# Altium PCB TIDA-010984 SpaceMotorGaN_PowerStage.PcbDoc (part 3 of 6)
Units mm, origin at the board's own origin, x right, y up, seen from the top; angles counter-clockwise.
Board outline 177.8 x 152.4 mm, 8 copper layers (Top Layer, DC LINK Layer 2, GND Layer 3, 3V3 Layer 4, Layer 5, Layer 6, GND Layer 7, Bottom Layer), stack 1.554 mm thick; 582 components, 280 nets, 1847 pads, 979 vias.
Unrouted connection lines stored in the file: 474.
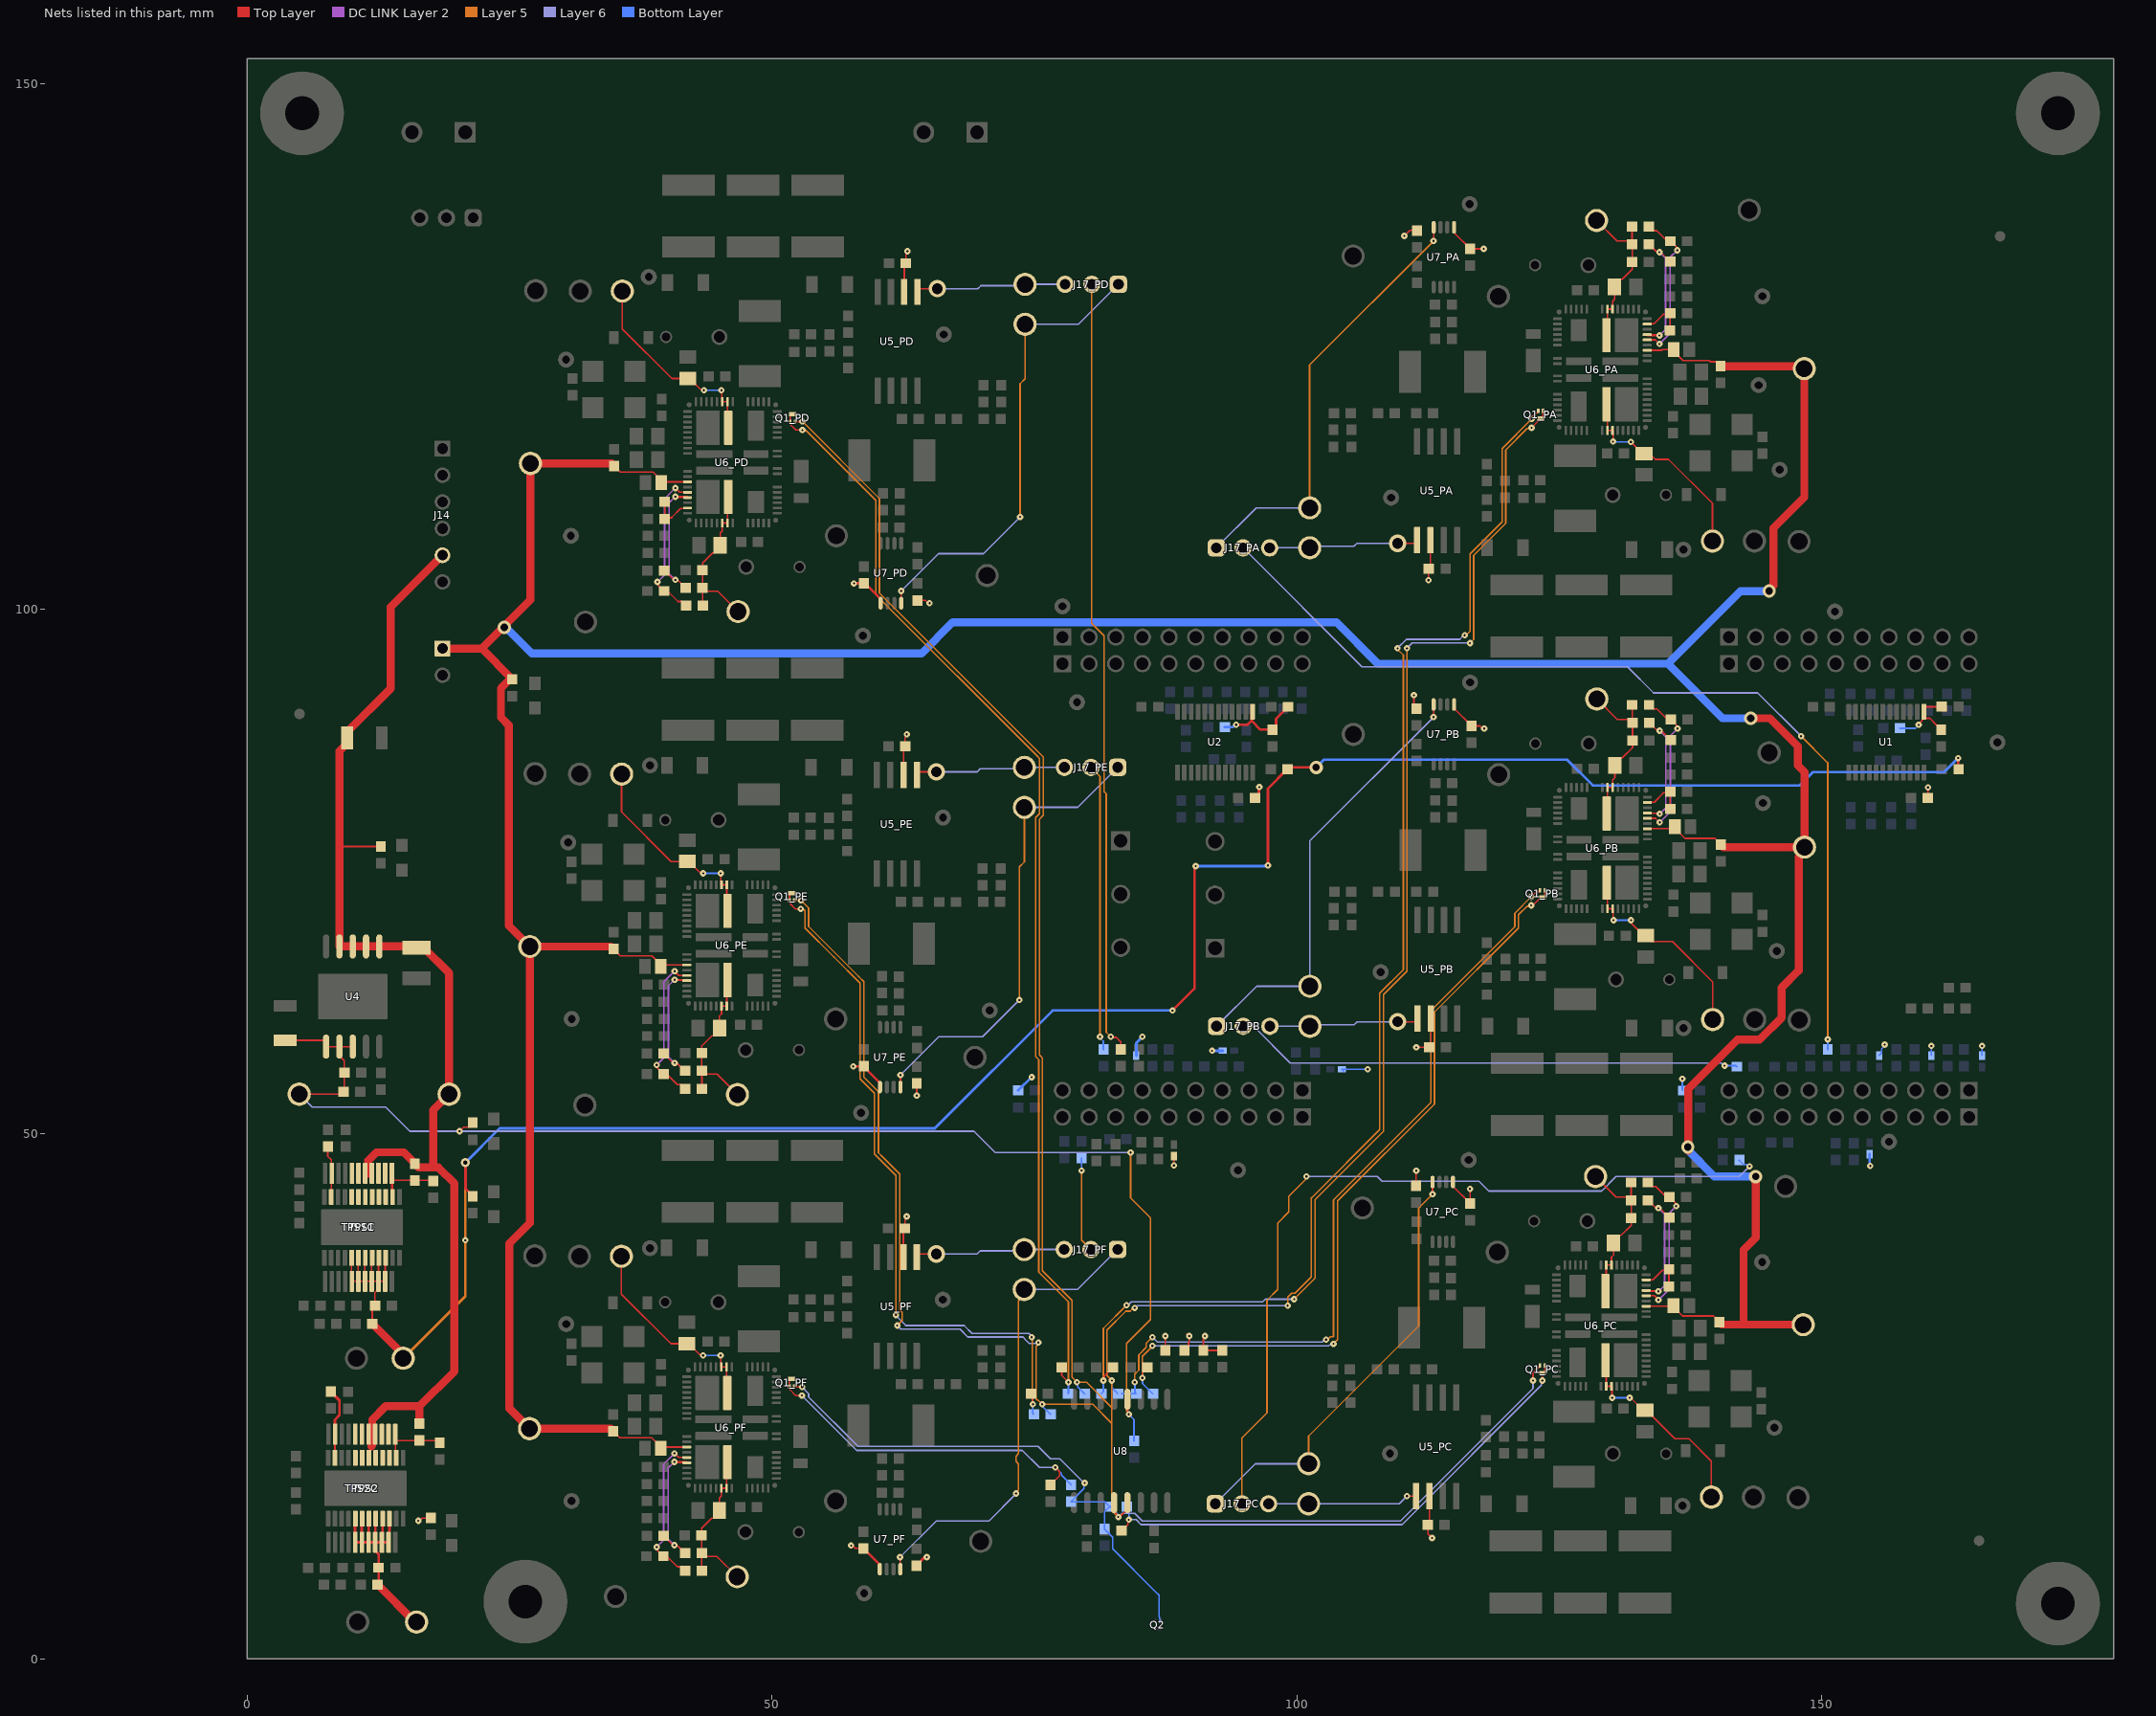
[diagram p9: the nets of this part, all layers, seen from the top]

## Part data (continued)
R78_PA R78_PB R78_PC R78_PD R78_PE R78_PF R80_PA R80_PB R80_PC R80_PD R80_PE R80_PF: library part CMP-0023006-4, "RES, 2.10, 1%, 0.1 W, 0603", Manufacturer=Yageo, Power_W=100mW, Supplier Part Number 1=311-2.10HRCT-ND, TempCo="200 ppm/C", Tolerance_%=1%, Value2=0.1W, Value_Code=2R10, ValueDisplayed=2.10
R82_PA R82_PB R82_PC R82_PD R82_PE R82_PF R83_PA R83_PB R83_PC R83_PD R83_PE R83_PF: library part CMP-0022206-4, "RES, 20.0, 1%, 0.1 W, AEC-Q200 Grade 0, 0603", Manufacturer=Vishay-Dale, Power_W=100mW, Supplier Part Number 1=541-20.0HCT-ND, TempCo="100 ppm/C", Tolerance_%=1%, Value2=0.1W, Value_Code=20R0, ValueDisplayed=20.0
R86_PA R86_PB R86_PC R86_PD R86_PE R86_PF: library part CMP-0023191-5, "RES, 57.6 k, 1%, 0.1 W, 0603", Manufacturer=Yageo, Power_W=100mW, Supplier Part Number 1=311-57.6KHRCT-ND, TempCo="100 ppm/C", Tolerance_%=1%, Value2=0.1W, Value_Code=57k6, ValueDisplayed=57.6k
R91_PA R91_PB R91_PC R91_PD R91_PE R91_PF: library part CMP-0023050-5, "RES, 35.7 k, 1%, 0.1 W, 0603", Manufacturer=Yageo, Power_W=100mW, Supplier Part Number 1=311-35.7KHRCT-ND, TempCo="100 ppm/C", Tolerance_%=1%, Value2=0.1W, Value_Code=35k7, ValueDisplayed=35.7k
R111: library part CMP-0023251-5, "RES, 6.65 k, 1%, 0.1 W, 0603", Manufacturer=Yageo, Power_W=100mW, Supplier Part Number 1=311-6.65KHRCT-ND, TempCo="100 ppm/C", Tolerance_%=1%, Value2=0.1W, Value_Code=6k65, ValueDisplayed=6.65k
R114: library part CMP-0022983-5, "RES, 2.10 k, 1%, 0.1 W, 0603", Manufacturer=Yageo, Power_W=100mW, Supplier Part Number 1=311-2.10KHRCT-ND, TempCo="100 ppm/C", Tolerance_%=1%, Value2=0.1W, Value_Code=2k10, ValueDisplayed=2.10k
TP1 TP3 TP5 TP7_PA TP7_PB TP7_PC TP7_PD TP7_PE TP7_PF TP8_PA TP8_PB TP8_PC TP8_PD TP8_PE TP8_PF TP9_PA TP9_PB TP9_PC TP9_PD TP9_PE TP9_PF TP10 TP11_PA TP11_PB TP11_PC TP11_PD TP11_PE TP11_PF: library part CMP-0055147-2, "Test Point, Multipurpose, Red, TH", Color=Red, Manufacturer="Keystone Electronics", Supplier Part Number 1=36-5010-ND
TP2 TP4: library part CMP-0055149-2, "Test Point, Multipurpose, White, TH", Color=White, Manufacturer="Keystone Electronics", Supplier Part Number 1=36-5012-ND
TP6_PA TP6_PB TP6_PC TP6_PD TP6_PE TP6_PF TP12_PA TP12_PB TP12_PC TP12_PD TP12_PE TP12_PF: library part CMP-0055160-2, "Test Point, Multipurpose, Purple, TH", Color=Purple, Manufacturer="Keystone Electronics", Supplier Part Number 1=36-5129-ND
TP10_PA TP10_PB TP10_PC TP10_PD TP10_PE TP10_PF: library part CMP-0055150-2, "Test Point, Multipurpose, Orange, TH", Color=Orange, Manufacturer="Keystone Electronics", Supplier Part Number 1=36-5013-ND
TP13_PA TP13_PB TP13_PC TP13_PD TP13_PE TP13_PF TP14_PA TP14_PB TP14_PC TP14_PD TP14_PE TP14_PF: library part CMP-0003907-1, "PIGTAIL", Manufacturer="Texas Instruments", PartNumber=TESTPOINT_PIGTAIL
TP16_PA TP16_PB TP16_PC TP16_PD TP16_PE TP16_PF TP17_PA TP17_PB TP17_PC TP17_PD TP17_PE TP17_PF TP18_PA TP18_PB TP18_PC TP18_PD TP18_PE TP18_PF: library part CMP-0055148-2, "Test Point, Multipurpose, Black, TH", Color=Black, Manufacturer="Keystone Electronics", Supplier Part Number 1=36-5011-ND
TPS1 TPS2: library part CMP-0122232-1, "2.25 V to 14-V Input, 2-A, Radiation Hardened LDO Regulator", Dropout Voltage=1000mV, Manufacturer="Texas Instruments", Max Supply Voltage=14V, Min Supply Voltage=2.25V, Nominal Supply Current=8-10mA, Operating Temperature Range="-55°C to +125°C", Output Voltage=0.6-13.9V
TPS1C TPS2C: library part CMP-0032523-3, "2.25 V to 14-V Input, 2-A, Radiation Hardened LDO Regulator", Dropout Voltage=1000mV, Manufacturer="Texas Instruments", Max Supply Voltage=14V, Min Supply Voltage=2.25V, Nominal Supply Current=10mA, Operating Temperature Range="-55°C to +125°C", Output Voltage=0.6-13.9V
U1 U2: library part CMP-0122972-1, "8-Bit Dual-Supply Bus Transceiver With Configurable Voltage Translation and Tri-State Outputs", Digikey Part Number=296-SN54SLC8T245PWTSEPCT-ND, Manufacturer="Texas Instruments", Mouser Part Number=595-54SLC8T245PWTSEP, Nominal Supply Current=70uA, Operating Temperature Range="-55°C to +125°C"
U4: library part CMP-0097443-1, "LDO Regulator Pos 1.21V to 20V 0.75A 10-Pin CFP Tube", Dropout Voltage=0.2V, Manufacturer="Texas Instruments", Max Supply Voltage=20V, Min Supply Voltage=2.9V, Nominal Supply Current=1-28mA, Operating Temperature Range="-55°C to +125°C", Output Voltage=1.21-20V
U5_PA U5_PB U5_PC U5_PD U5_PE U5_PF: library part CMP-0081563-2, "Voltage Output, Unidirectional Measurement Current-Shunt Monitor, HKX0008A (CFP-8)", Alternate Manufacturer="Texas Instruments", Rating=Space
U6_PA U6_PB U6_PC U6_PD U6_PE U6_PF: library part CMP-0121940-3, "200-V, 12-A eGaN Half Bridge Power Stage with Integrated Driver", Manufacturer="Texas Instruments", Max Supply Voltage=16V, Min Supply Voltage=10V, Operating Temperature Range="-55°C to +125°C"
U7_PA U7_PB U7_PC U7_PD U7_PE U7_PF: library part CMP-0075734-1, "High/Low Side, Bi-Directional Zero-Drift Current Sense Amp w/ Enhanced PWM Rejection, PW0008A (TSSOP-8)", Alternate Manufacturer="Texas Instruments", Alternate PartNumber=INA240A1PW
U8: library part CMP-0097071-1, "9-Channel (8-Remote and 1-Local), High-Accuracy Temperature Sensor", Manufacturer="Texas Instruments", Max Supply Voltage=3.6V, Min Supply Voltage=1.7V, Mouser Part Number=595-5962R2021401VXC, Operating Temperature Range="-55°C to +125°C"
ZZ1: library part CMP-0003616-3
ZZ2: library part CMP-0077236-1
ZZ3: library part CMP-0077237-1
ZZ4: library part CMP-0077238-1

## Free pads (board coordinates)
  round 1.524 hole 0.762: 8(30.847,106.96) 8(30.918,15.024) 8(30.932,60.948) 8(58.5,52) 8(58.679,97.465) 8(58.788,6.239) 8(116.38,47.513) 8(116.478,138.569) 8(116.5,93) 8(136.834,60.074) 8(144,121.315) 8(144.337,37.787) 8(144.348,129.784) 8(144.42,81.513) 8(151.27,99.75) 9(30.391,123.75) 9(30.402,31.882) 9(30.594,77.75) 9(66.288,34.206) 9(66.302,80.13) 9(66.37,126.142) 9(107.994,65.421) 9(108.88,19.546) 9(108.978,110.602) 9(145.5,22) 9(145.726,67.426) 9(146,113.25) 10(38.273,131.62) 10(38.379,39.118) 10(38.393,85.089) 10(94.397,46.551) 10(136.743,14.57) 10(136.826,105.643) 10(156.416,49.25) 10(166.75,87.3) 11(79.068,91.113) 12(70.75,61.75) 13(77.676,100.25)

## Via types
v1: diameter 0.61, hole 0.2, Top Layer to Bottom Layer, tented both sides, 306 vias
v2: diameter 0.61, hole 0.203, Top Layer to Bottom Layer, tented both sides, 272 vias
v3: diameter 0.5, hole 0.2, Top Layer to Bottom Layer, tented both sides, 216 vias
v4: diameter 0.5, hole 0.2, Top Layer to Bottom Layer, 66 vias
v5: diameter 0.61, hole 0.2, Top Layer to Bottom Layer, 61 vias
v6: diameter 0.864, hole 0.406, Top Layer to Bottom Layer, tented both sides, 17 vias
v7: diameter 1.651, hole 1.016, Top Layer to Bottom Layer, tented both sides, 12 vias
v8: diameter 0.864, hole 0.406, Top Layer to Bottom Layer, 9 vias
v9: diameter 0.61, hole 0.203, Top Layer to Bottom Layer, 8 vias
v10: diameter 1.27, hole 0.711, Top Layer to Bottom Layer, tented both sides, 5 vias
v11: diameter 0.61, hole 0.2, Top Layer to Bottom Layer, tented top, 2 vias
v12: diameter 1.651, hole 1.016, Top Layer to Bottom Layer, 2 vias
v13: diameter 0.61, hole 0.203, Top Layer to Bottom Layer, tented bottom, 1 vias
v14: diameter 1.27, hole 0.711, Top Layer to Bottom Layer, 1 vias
v15: diameter 1.651, hole 1.016, Top Layer to Bottom Layer, tented top, 1 vias

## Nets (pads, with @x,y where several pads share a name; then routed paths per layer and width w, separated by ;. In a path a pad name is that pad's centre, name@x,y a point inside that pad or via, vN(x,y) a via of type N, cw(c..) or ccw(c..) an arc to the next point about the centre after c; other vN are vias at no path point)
2V: C29.1 C30.1 C57.2 R73.2 R114.2 TP5.1 U4.6 U4.7 U4.8 U8.12 | length 129.7
  Top Layer w0.152: C30.1@3.626,58.906 7.322,58.906 7.529,58.699 U4.6@7.529,58.306 U4.7@8.799,58.306 ; TP5.1@4.973,53.784 8.976,53.784 R73.2@9.192,53.999 9.269,54.076 C29.1@9.269,55.847 9.269,56.986 8.799,57.456 U4.7@8.799,58.306 ; U4.8@10.069,58.306 U4.7@8.799,58.306 ; v5(20.25,50.25) 20.627,50.627 21.101,50.627 21.5,51.026 R114.2@21.5,51.05 ; U8.12@83.934,24.657 83.934,23.356 v1(84,23.29)
  Layer 5 w0.152: v1(84,23.29) 84,23.401 83.794,23.608 83.794,30.044 86.063,32.313 86.063,42 84.169,43.894 v1(84.169,48.22)
  Layer 6 w0.152: TP5.1@4.973,53.784 6.212,52.545 13.205,52.545 15.5,50.25 v5(20.25,50.25) 69.25,50.25 71.28,48.22 v1(84.169,48.22)
  Bottom Layer w0.152: v1(84,23.29) 84.5,22.79 C57.2@84.5,20.744
3V3: C1.1 C11.1 C31_PA.1 C31_PB.1 C31_PC.1 C31_PD.1 C31_PE.1 C31_PF.1 C50_PA.2 C50_PB.2 C50_PC.2 C50_PD.2 C50_PE.2 C50_PF.2 D1.1 D2.1 D3.1 D4.1 D5.1 D6.1 D7.1 D16.1 R1.1 R8.2 R9.2 R12.1 R29.1 R35.2 R36.2 R65.1 R67.1 R94_PA.1 R94_PB.1 R94_PC.1 R94_PD.1 R94_PE.1 R94_PF.1 R96.2 R97.2 R98.2 R99.2 R109.1 R112.2 TP3.1 TPS2.17 TPS2.18 TPS2.19 TPS2.20 TPS2.21 TPS2.22 TPS2C.16 TPS2C.17 TPS2C.18 TPS2C.19 TPS2C.20 TPS2C.21 U1.1 U2.1 U5_PA.6 U5_PB.6 U5_PC.6 U5_PD.6 U5_PE.6 U5_PF.6 U7_PA.5 U7_PB.5 U7_PC.5 U7_PD.5 U7_PE.5 U7_PF.5 | length 123.6
  Top Layer w0.152: v5(16.318,13.154) 16.442,13.154 16.684,13.396 17.456,13.396 R112.2@17.5,13.44 ; v5(57.545,10.789) 57.668,10.789 57.943,10.514 C50_PF.2@58.736,10.514 ; U5_PF.6@62.527,38.262 62.527,40.844 C31_PF.1@62.679,40.996 62.679,41.858 62.837,42.016 v1(62.837,42.14) ; U5_PE.6@62.541,84.186 62.541,86.768 C31_PE.1@62.693,86.92 62.693,87.782 62.851,87.94 v1(62.851,88.064) ; U5_PD.6@62.609,130.198 62.609,132.78 C31_PD.1@62.761,132.932 62.761,133.794 62.919,133.952 v1(62.919,134.076) ; v1(63.797,53.654) R94_PE.1@63.797,54.807 ; R94_PD.1@63.879,100.819 64.624,100.819 64.895,100.547 v1(65.019,100.547) ; R96.2@87.471,29.381 v1(87.471,30.745) ; v1(88.307,47) D7.1@88.307,47.878 ; R97.2@89.285,29.381 89.684,29.78 89.684,30.136 89.75,30.202 v1(89.75,30.745) 89.695,30.745 89.5,30.94 ; v1(91.25,30.745) 91.25,30.621 91.099,30.47 R99.2@91.099,29.381 R98.2@92.913,29.381 ; v5(110.25,135.522) 110.778,136.05 R94_PA.1@111.469,136.05 ; v1(111.155,91.785) 111.155,90.743 R94_PB.1@111.403,90.495 R94_PB.1@111.441,90.532 ; R94_PC.1@111.371,45.05 v5@111.371,46.25 ; v11(111.391,58.235) 112.602,58.235 112.761,58.395 U5_PB.6@112.761,60.977 ; v1(112.556,102.744) 112.556,103.78 C31_PA.1@112.587,103.812 112.739,103.964 U5_PA.6@112.739,106.546 ; U5_PC.6@112.641,15.49 112.641,12.908 C31_PC.1@112.489,12.756 112.489,11.894 v1(112.883,11.5) ; U7_PC.5@114.886,45.413 114.886,45.002 C50_PC.2@116.5,43.388 ; U7_PB.5@114.984,90.899 114.984,90.532 116.642,88.874 C50_PB.2@116.642,88.849 117.481,88.849 117.731,88.6 v5(117.855,88.6) ; U7_PA.5@114.984,136.35 115.031,136.303 115.031,135.794 116.5,134.325 C50_PA.2@116.5,134.3 v5(117.817,134.3) ; C50_PC.2@116.5,43.363 C50_PC.2@116.5,43.388 ; v5(116.5,44.75) C50_PC.2@116.5,43.388 ; v1@159.173,88.961 159.592,89.38 159.592,90.067 U1.1@159.741,90.216 ; R8.2@160.116,82 160.116,81.952 160.131,81.936 v1(160.131,83) ; R1.1@161.386,88.509 161.386,88.534 160.988,88.933 160.963,88.933 160.304,89.592 159.889,89.592 159.741,89.74 U1.1@159.741,90.216 ; R9.2@161.45,90.683 159.889,90.683 159.741,90.535 U1.1@159.741,90.216
  Top Layer w0.254: TPS2.17@10.317,13.34 10.296,13.32 10.296,11.116 10.276,11.095 TPS2C.16@10.308,11.095 TPS2C.17@10.911,11.095 ; TPS2.18@10.967,13.34 10.939,13.312 10.939,11.123 TPS2C.17@10.911,11.095 ; TPS2.19@11.617,13.34 11.581,13.305 11.581,11.131 TPS2C.18@11.546,11.095 ; TPS2.20@12.267,13.34 12.224,13.297 TPS2C.19@12.224,11.095 ; R67.1@12.442,7.069 R67.1@12.417,7.069 12.541,7.193 R65.1@12.541,8.684 12.541,9.953 12.224,10.27 TPS2C.19@12.224,11.095 ; TPS2.21@12.917,13.34 12.917,11.979 12.816,11.878 TPS2C.20@12.816,11.095 ; TPS2.22@13.567,13.34 13.567,12.227 13.541,12.201 13.541,11.186 13.451,11.095 TPS2C.20@12.848,11.095 TPS2C.20@12.816,11.095 ; TP3.1@16.01,3.5 TP3.1@16.153,3.5 ; v1(57.75,56.418) 58.73,56.418 C50_PE.2@58.75,56.438 ; v1(57.818,102.43) 58.73,102.43 C50_PD.2@58.75,102.45 ; C50_PF.2@58.736,10.489 60.282,8.943 U7_PF.5@60.282,8.536 ; C50_PE.2@58.75,56.413 60.296,54.867 U7_PE.5@60.296,54.46 ; C50_PD.2@58.75,102.425 59.098,102.077 59.234,102.077 60.364,100.947 U7_PD.5@60.364,100.547 ; R94_PE.1@63.691,54.701 R94_PE.1@63.797,54.807 ; R94_PF.1@63.783,8.882 63.783,8.907 64.49,9.614 64.682,9.614 v5(64.75,9.682) ; v1(94.227,88.968) 95.301,88.968 95.693,89.359 ; U2.1@95.791,90.216 95.693,90.118 95.693,89.359 ; R35.2@96.195,81.811 R35.2@96.006,82 96.031,82 96.379,82.348 96.379,82.971 v1(96.442,83.035) ; R29.1@97.681,88.484 R29.1@97.681,88.509 ; R36.2@99.189,90.682 99.164,90.682 98.029,89.547 98.029,88.857 R29.1@97.681,88.509 ; TPS2C.17@10.911,11.095 TPS2C.17@10.943,11.095 TPS2C.18@11.546,11.095 ; TPS2C.18@11.546,11.095 TPS2C.18@11.578,11.095 TPS2C.19@12.213,11.095 TPS2C.19@12.224,11.095 ; TPS2C.19@12.224,11.095 TPS2C.20@12.816,11.095 ; 95.693,89.359 96.543,88.509 R29.1@97.681,88.509
  Top Layer w0.762: R67.1@12.417,7.069 12.442,7.069 16.01,3.5 TP3.1@16.153,3.5
  Layer 6 w0.254: TP3.1@15.592,3.5 TP3.1@16.153,3.5
  Bottom Layer w0.152: D16.1@104.449,56 D16.1@104.3,56.149 v9(106.75,56.149) ; v1(136.723,55.25) 136.723,54.223 R12.1@136.804,54.142 ; D2.1@155.497,57.464 155.721,57.688 155.721,58.097 156,58.376 v1(156,58.5) ; C1.1@157.471,88.636 158.925,88.636 v1(159.25,88.961) ; D3.1@160.447,57.464 v1(160.447,58.376) ; D1.1@165.29,57.464 v1(165.29,58.376)
  Bottom Layer w0.254: R109.1@73.45,54.142 73.475,54.142 74.727,55.394 v9(74.75,55.394) ; D5.1@84.709,57.462 84.709,58.662 v1(85.296,59.248) ; v1@91.844,58.036 91.844,58.006 v1(91.931,57.919) D6.1@92.939,57.919 ; C11.1@93.166,88.75 93.914,88.75 94.132,88.968 v1(94.227,88.968) ; D4.1@154.577,48.069 154.577,46.993 v1(154.632,46.938)
  other v5: 111.391,46.497
5V: R2.1 R30.1 R55.1 R59.1 R111.2 TP1.1 TPS1.17 TPS1.18 TPS1.19 TPS1.20 TPS1.21 TPS1.22 TPS1C.16 TPS1C.17 TPS1C.18 TPS1C.19 TPS1C.20 TPS1C.21 | length 222.6
  Top Layer w0.152: TPS1.17@9.968,38.198 9.947,38.178 9.947,35.974 9.927,35.953 TPS1C.17@10.562,35.953 ; TPS1.18@10.618,38.198 10.59,38.17 10.59,35.981 TPS1C.17@10.562,35.953 ; TPS1.19@11.268,38.198 11.232,38.163 11.232,35.989 TPS1C.18@11.197,35.953 ; TPS1.20@11.918,38.198 11.875,38.155 11.875,35.996 TPS1C.19@11.832,35.953 ; R59.1@11.932,31.892 11.932,33.382 R55.1@12.192,33.642 12.192,34.896 12.467,35.171 TPS1C.20@12.467,35.953 ; TPS1.21@12.568,38.198 12.517,38.148 12.517,36.004 TPS1C.20@12.467,35.953 ; TPS1.22@13.218,38.198 13.16,38.14 13.16,36.011 13.102,35.953 TPS1C.20@12.467,35.953 ; TPS1C.17@10.562,35.953 TPS1C.18@11.197,35.953 ; TPS1C.18@11.197,35.953 TPS1C.19@11.832,35.953 ; TPS1C.19@11.832,35.953 TPS1C.20@12.467,35.953
  Top Layer w0.254: R59.1@11.932,31.892 R59.1@11.957,31.892 ; TP1.1@14.875,28.624 TP1.1@14.875,28.974 ; v6(20.792,47.25) 20.807,47.235 20.807,44.768 21.5,44.075 R111.2@21.5,44.05 ; v1(88.155,61.75) 90.25,63.845 90.25,75.282 90.376,75.408 v1(90.376,75.5) ; v1(97.25,75.576) 97.25,82.893 R30.1@99.104,84.747 ; R30.1@99.129,84.747 99.293,84.911 v14(101.84,84.911) ; v1(163,85.792) 163,84.797 R2.1@163.05,84.747
  Top Layer w0.762: R59.1@11.957,31.892 TP1.1@14.875,28.974
  Layer 5 w0.254: TP1.1@14.875,28.624 20.792,34.541 v1(20.792,39.867) v6(20.792,47.25)
  Layer 6 w0.254: v1(20.792,39.867) v1@20.888,39.867
  Bottom Layer w0.254: v6(20.792,47.25) 24.056,50.514 65.514,50.514 76.75,61.75 v1(88.155,61.75) ; v1(90.376,75.5) 97.101,75.5 97.177,75.576 v1(97.25,75.576) ; v14(101.84,84.911) 102.576,85.647 125.75,85.647 128.206,83.191 147.891,83.191 149.158,84.457 161.665,84.457 v1(163,85.792)
12Vp: C23.1 C24.1 J14.5 R54.2 R64.2 R102.2 TP10.1 TPS1.3 TPS1.4 TPS1.5 TPS1.6 TPS1.7 TPS1.8 TPS1C.2 TPS1C.3 TPS1C.4 TPS1C.5 TPS1C.6 TPS1C.7 TPS2.3 TPS2.4 TPS2.5 TPS2.6 TPS2.7 TPS2.8 TPS2C.2 TPS2C.3 TPS2C.4 TPS2C.5 TPS2C.6 TPS2C.7 U4.1 U4.2 U4.3 U4.4 | length 118.4
  Top Layer w0.152: 8.799,77.472 8.903,77.369 R102.2@12.75,77.369
  Top Layer w0.762: 11.546,46.206 11.546,47.467 12.329,48.25 14.931,48.25 15.985,47.196 R54.2@15.985,47.171 ; 11.832,20.213 11.932,20.313 11.932,22.77 13.229,24.068 16.429,24.068 ; R54.2@16.333,46.798 17.725,46.798 ; R64.2@16.429,22.386 16.429,24.068 ; J14.5@18.62,105.115 13.694,100.189 13.694,92.436 9.533,88.275 C24.1@9.533,87.725 9.533,87.175 8.799,86.441 8.799,77.472 U4.4@8.799,67.856 U4.3@10.069,67.856 U4.2@11.339,67.856 U4.1@12.609,67.856 16.01,67.856 C23.1@16.142,67.724 16.842,67.724 19.25,65.316 TP10.1@19.25,53.784 17.725,52.259 17.725,46.798 ; 16.429,24.068 19.75,27.389 19.75,45.28 18.232,46.798 17.725,46.798
12Vs: C44_PA.2 C44_PB.2 C44_PC.2 C44_PD.2 C44_PE.2 C44_PF.2 J15.1 R78_PA.2 R78_PB.2 R78_PC.2 R78_PD.2 R78_PE.2 R78_PF.2 R110.2 TP7_PA.1 TP7_PB.1 TP7_PC.1 TP7_PD.1 TP7_PE.1 TP7_PF.1 U6_PA.13 U6_PB.13 U6_PC.13 U6_PD.13 U6_PE.13 U6_PF.13 | length 429.2
  Top Layer w0.152: R78_PF.2@34.892,21.683 34.892,21.658 35.291,21.259 35.316,21.259 35.531,21.044 38.549,21.044 39.406,20.187 C44_PF.2@39.406,20.037 ; R78_PE.2@34.906,67.608 34.906,67.583 35.304,67.184 35.329,67.184 35.545,66.968 38.563,66.968 39.42,66.112 C44_PE.2@39.42,65.962 ; R78_PD.2@34.974,113.619 34.974,113.594 35.373,113.196 35.398,113.196 35.571,113.022 38.691,113.022 38.978,112.734 38.978,112.508 C44_PD.2@39.452,112.034 ; C44_PF.2@39.467,19.977 39.663,20.173 U6_PF.13@41.884,20.173 ; C44_PE.2@39.48,65.901 39.677,66.097 U6_PE.13@41.898,66.097 ; C44_PD.2@39.488,111.973 C44_PD.2@39.488,112.123 ; C44_PD.2@39.549,111.913 39.745,112.109 U6_PD.13@41.966,112.109 ; U6_PC.13@133.284,33.579 135.655,33.579 135.798,33.722 135.798,33.59 136.36,33.027 136.377,33.027 136.56,32.844 136.56,32.837 136.743,32.654 139.691,32.654 139.852,32.492 139.877,32.492 140.276,32.094 R78_PC.2@140.276,32.069 ; U6_PA.13@133.382,124.635 134.766,124.635 134.845,124.713 C44_PA.2@135.888,124.713 135.888,124.563 136.797,123.653 139.298,123.653 139.403,123.548 139.975,123.548 140.374,123.149 R78_PA.2@140.374,123.124 ; U6_PB.13@133.404,79.066 135.775,79.066 135.918,79.209 136.986,78.141 139.836,78.141 140.609,77.368 R78_PB.2@140.609,77.318
  Top Layer w0.762: J15.1@18.62,96.225 22.35,96.225 ; R110.2@24.934,93.181 24.194,92.441 24.194,89.668 24.934,88.927 24.934,69.842 TP7_PE.1@26.932,67.845 ; R110.2@25.25,93.325 22.35,96.225 ; R78_PF.2@34.892,21.683 34.892,21.708 34.798,21.802 34.773,21.802 34.654,21.921 TP7_PF.1@26.918,21.921 25,23.839 25,39.568 26.932,41.499 TP7_PE.1@26.932,67.845 ; R78_PE.2@34.906,67.608 34.906,67.633 34.812,67.727 34.787,67.727 34.668,67.845 TP7_PE.1@26.932,67.845 ; R78_PD.2@34.974,113.619 34.974,113.644 34.88,113.738 34.855,113.738 34.736,113.857 TP7_PD.1@27,113.857 27,100.876 22.35,96.225 ; v10@137.307,48.406 137.307,54.31 141.966,58.969 144.082,58.969 146.184,61.071 146.184,63.91 147.822,65.548 147.822,76.378 148.37,76.926 TP7_PB.1@148.37,77.318 ; R78_PC.2@140.276,32.069 140.276,32.044 140.488,31.831 143.716,31.831 TP7_PC.1@148.25,31.831 ; R78_PA.2@140.374,123.124 148.11,123.124 TP7_PA.1@148.348,122.887 148.348,110.635 145.404,107.691 145.404,102.245 145,101.841 v10(145,101.704) ; R78_PB.2@140.609,77.318 TP7_PB.1@148.37,77.318 ; 142.568,31.831 142.568,38.945 143.716,40.093 v10(143.716,45.938) ; v10(143.25,89.592) 145.068,89.592 147.75,86.909 147.75,85.092 148.37,84.471 TP7_PB.1@148.37,77.318
  Bottom Layer w0.762: v10(24.5,98.25) 24.637,98.25 27.137,95.75 64.25,95.75 67.228,98.728 103.772,98.728 107.718,94.782 135.356,94.782 ; v10@137.307,48.406 139.776,45.938 v10(143.716,45.938) ; v10(143.25,89.592) 140.547,89.592 135.356,94.782 ; v10(145,101.704) 142.277,101.704 135.356,94.782
  other v10: 137.25,48.75
BP5H_PA: C55_PA.2 TP11_PA.1 U6_PA.58 U6_PA.59 U6_PA.74 | length 19.2
  Top Layer w0.152: U6_PA.74@129.507,119.492 129.583,119.416 U6_PA.58@129.583,117.01 U6_PA.59@130.083,117.01 130.132,116.961 v1(130.132,115.94) v1@130.155,115.917 ; v1(131.819,115.917) 131.819,115.909 132.918,114.81 C55_PA.2@133.083,114.81 ; C55_PA.2@133.591,114.81 134.149,114.251 135.411,114.251 139.598,110.064 TP11_PA.1@139.598,106.46
  Bottom Layer w0.152: v1@130.193,115.955 130.155,115.917 v1(131.819,115.917)
BP5H_PB: C55_PB.2 TP11_PB.1 U6_PB.58 U6_PB.59 U6_PB.74 | length 19.7
  Top Layer w0.152: U6_PB.74@129.529,73.923 129.605,73.847 U6_PB.58@129.605,71.441 U6_PB.59@130.105,71.441 130.154,71.392 130.154,70.371 v1(130.177,70.348) ; v1@131.841,70.34 v1(131.841,70.348) 131.929,70.26 131.929,70.018 133.074,68.873 C55_PB.2@133.239,68.873 133.798,68.314 135.784,68.314 139.62,64.478 TP11_PB.1@139.62,60.891
  Bottom Layer w0.152: v1(130.177,70.348) v1(131.841,70.348)
BP5H_PC: C55_PC.2 TP11_PC.1 U6_PC.58 U6_PC.59 U6_PC.74 | length 19.6
  Top Layer w0.152: U6_PC.74@129.409,28.436 129.485,28.36 U6_PC.58@129.485,25.954 U6_PC.59@129.985,25.954 130.034,25.905 130.034,24.884 v1(130.057,24.861) ; v1@131.721,24.853 v1(131.721,24.861) 131.808,24.861 133.007,23.662 C55_PC.2@133.172,23.662 133.337,23.662 136.033,20.966 137.363,20.966 139.5,18.828 TP11_PC.1@139.5,15.404
  Bottom Layer w0.152: v1@130.095,24.9 v1(130.057,24.861) v1(131.721,24.861)
BP5H_PD: C55_PD.2 TP11_PD.1 U6_PD.58 U6_PD.59 U6_PD.74 | length 19.7
  Top Layer w0.152: TP11_PD.1@35.75,130.284 35.75,126.679 40.477,121.953 C55_PD.2@41.992,121.953 42.157,121.953 43.195,120.914 43.442,120.914 v1(43.529,120.827) v1@43.529,120.835 ; v1(45.193,120.827) 45.216,120.804 45.216,119.783 U6_PD.59@45.265,119.734 U6_PD.58@45.765,119.734 45.765,117.328 U6_PD.74@45.841,117.252
  Bottom Layer w0.152: v1(43.529,120.827) v1(45.193,120.827) v1@45.155,120.788
BP5H_PE: C55_PE.2 TP11_PE.1 U6_PE.58 U6_PE.59 U6_PE.74 | length 19.7
  Top Layer w0.152: TP11_PE.1@35.682,84.272 35.682,80.667 40.408,75.941 C55_PE.2@41.924,75.941 42.089,75.941 43.127,74.903 43.373,74.903 v1(43.461,74.815) v1@43.461,74.823 ; v1(45.125,74.815) 45.148,74.792 45.148,73.771 U6_PE.59@45.197,73.722 U6_PE.58@45.697,73.722 45.697,71.316 U6_PE.74@45.773,71.24
  Bottom Layer w0.152: v1(43.461,74.815) v1(45.125,74.815) v1@45.086,74.777
BP5H_PF: C55_PF.2 TP11_PF.1 U6_PF.58 U6_PF.59 U6_PF.74 | length 19.7
  Top Layer w0.152: TP11_PF.1@35.668,38.348 35.668,34.743 40.395,30.016 C55_PF.2@41.91,30.016 42.075,30.016 43.113,28.978 43.359,28.978 v1(43.447,28.891) v1@43.447,28.899 ; v1(45.111,28.891) 45.134,28.868 45.134,27.847 U6_PF.59@45.183,27.798 U6_PF.58@45.683,27.798 45.683,25.392 U6_PF.74@45.759,25.316
  Bottom Layer w0.152: v1(43.447,28.891) v1(45.111,28.891) v1@45.073,28.852
BP5L_PA: C52_PA.2 R81_PA.2 R84_PA.1 R87_PA.1 TP9_PA.1 U6_PA.26 U6_PA.27 U6_PA.69 | length 16.1
  Top Layer w0.152: TP9_PA.1@128.565,136.994 130.513,135.045 131.637,135.045 R87_PA.1@131.949,134.734 ; U6_PA.69@129.507,126.078 129.583,126.154 U6_PA.27@129.583,128.56 U6_PA.26@130.083,128.56 130.083,129.311 130.271,129.499 C52_PA.2@130.271,130.675 130.271,130.84 130.83,131.399 130.995,131.399 131.958,132.362 R81_PA.2@131.958,133.046 131.958,134.725 R87_PA.1@131.949,134.734 ; R84_PA.1@131.937,136.43 131.949,136.418 R87_PA.1@131.949,134.734
BP5L_PB: C52_PB.2 R81_PB.2 R84_PB.1 R87_PB.1 TP9_PB.1 U6_PB.26 U6_PB.27 U6_PB.69 | length 16.1
  Top Layer w0.152: TP9_PB.1@128.587,91.425 130.535,89.476 131.659,89.476 R87_PB.1@131.971,89.165 ; U6_PB.69@129.529,80.509 129.605,80.585 U6_PB.27@129.605,82.991 U6_PB.26@130.105,82.991 130.105,83.742 130.293,83.93 C52_PB.2@130.293,85.106 130.293,85.271 130.852,85.83 131.017,85.83 131.98,86.793 R81_PB.2@131.98,87.477 131.98,89.156 R87_PB.1@131.971,89.165 ; R84_PB.1@131.959,90.861 131.971,90.849 R87_PB.1@131.971,89.165
BP5L_PC: C52_PC.2 R81_PC.2 R84_PC.1 R87_PC.1 TP9_PC.1 U6_PC.26 U6_PC.27 U6_PC.69 | length 16.1
  Top Layer w0.152: TP9_PC.1@128.467,45.938 130.415,43.99 131.539,43.99 R87_PC.1@131.851,43.678 ; U6_PC.69@129.409,35.022 129.485,35.098 U6_PC.27@129.485,37.504 U6_PC.26@129.985,37.504 129.985,38.256 130.173,38.444 C52_PC.2@130.173,39.619 130.173,39.784 130.732,40.343 130.897,40.343 131.86,41.306 R81_PC.2@131.86,41.99 131.86,43.669 R87_PC.1@131.851,43.678 ; R84_PC.1@131.839,45.374 131.851,45.362 R87_PC.1@131.851,43.678
BP5L_PD: C52_PD.2 R81_PD.2 R84_PD.1 R87_PD.1 TP9_PD.1 U6_PD.26 U6_PD.27 U6_PD.69 | length 16.1
  Top Layer w0.152: R84_PD.1@43.411,100.314 43.399,100.326 R87_PD.1@43.399,102.01 ; U6_PD.69@45.841,110.666 45.765,110.59 U6_PD.27@45.765,108.184 U6_PD.26@45.265,108.184 45.265,107.433 45.077,107.245 C52_PD.2@45.077,106.069 45.077,105.904 44.518,105.345 44.353,105.345 43.39,104.382 R81_PD.2@43.39,103.698 43.39,102.019 R87_PD.1@43.399,102.01 ; TP9_PD.1@46.783,99.75 44.835,101.698 43.711,101.698 R87_PD.1@43.399,102.01
BP5L_PE: C52_PE.2 R81_PE.2 R84_PE.1 R87_PE.1 TP9_PE.1 U6_PE.26 U6_PE.27 U6_PE.69 | length 16.1
  Top Layer w0.152: R84_PE.1@43.343,54.302 43.331,54.314 R87_PE.1@43.331,55.998 ; U6_PE.69@45.773,64.654 45.697,64.578 U6_PE.27@45.697,62.172 U6_PE.26@45.197,62.172 45.197,61.421 45.009,61.233 C52_PE.2@45.009,60.057 45.009,59.892 44.45,59.333 44.285,59.333 43.322,58.37 R81_PE.2@43.322,57.686 43.322,56.007 R87_PE.1@43.331,55.998 ; TP9_PE.1@46.715,53.738 44.766,55.687 43.642,55.687 R87_PE.1@43.331,55.998
BP5L_PF: C52_PF.2 R81_PF.2 R84_PF.1 R87_PF.1 TP9_PF.1 U6_PF.26 U6_PF.27 U6_PF.69 | length 16.1
  Top Layer w0.152: R84_PF.1@43.329,8.378 43.317,8.39 R87_PF.1@43.317,10.074 ; U6_PF.69@45.759,18.73 45.683,18.654 U6_PF.27@45.683,16.248 U6_PF.26@45.183,16.248 45.183,15.496 44.995,15.308 C52_PF.2@44.995,14.133 44.995,13.968 44.436,13.409 44.271,13.409 43.308,12.446 R81_PF.2@43.308,11.762 43.308,10.083 R87_PF.1@43.317,10.074 ; TP9_PF.1@46.701,7.814 44.753,9.762 43.629,9.762 R87_PF.1@43.317,10.074
CL3: R68.2 TPS2.11 TPS2C.10 | length 6.8
  Top Layer w0.152: TPS2.11@8.367,19.14 8.369,19.142 TPS2C.10@8.369,21.383
  Top Layer w0.254: R68.2@8.004,25.441 8.004,25.416 8.806,24.614 8.806,23.206 8.371,22.77 8.371,21.385 TPS2C.10@8.369,21.383
CL5: R60.2 TPS1.11 TPS1C.10 | length 4.9
  Top Layer w0.152: R60.2@7.712,48.786 7.69,48.763 7.69,47.86 8.022,47.528 8.022,46.243 8.02,46.241 8.02,44 TPS1.11@8.018,43.998
CS_HiSide_PA: J17_PA.3 TP6_PA.1 U5_PA.5 | length 14.6
  Top Layer w0.152: v7(109.598,106.244) 111.245,106.244 111.469,106.468 U5_PA.5@111.469,106.546
  Layer 5 w0.152: TP6_PA.1@101.228,105.821 TP6_PA.1@101.364,105.958
  Layer 6 w0.152: J17_PA.3@97.418,105.821 TP6_PA.1@101.228,105.821 101.364,105.958 105.442,105.958 105.728,106.244 v7(109.598,106.244)
CS_HiSide_PB: J17_PB.3 TP6_PB.1 U5_PB.5 | length 14.6
  Top Layer w0.152: v7(109.62,60.675) 111.267,60.675 111.491,60.899 U5_PB.5@111.491,60.977
  Layer 5 w0.152: TP6_PB.1@101.25,60.252 TP6_PB.1@101.386,60.389
  Layer 6 w0.152: J17_PB.3@97.44,60.252 TP6_PB.1@101.25,60.252 101.386,60.389 105.464,60.389 105.75,60.675 v7(109.62,60.675)
CS_HiSide_PC: J17_PC.3 TP6_PC.1 U5_PC.5 | length 14.6
  Top Layer w0.152: v1(110.49,15.49) U5_PC.5@111.371,15.49
  Layer 5 w0.152: TP6_PC.1@101.13,14.766 TP6_PC.1@101.266,14.902
  Layer 6 w0.152: J17_PC.3@97.32,14.766 TP6_PC.1@101.13,14.766 109.766,14.766 v1(110.49,15.49) v1@110.5,15.5
CS_HiSide_PD: J17_PD.3 TP6_PD.1 U5_PD.5 | length 14.6
  Top Layer w0.152: U5_PD.5@63.879,130.198 63.879,130.276 64.103,130.5 v7(65.75,130.5)
  Layer 5 w0.152: TP6_PD.1@73.984,130.786 TP6_PD.1@74.12,130.923
  Layer 6 w0.152: v7(65.75,130.5) 69.62,130.5 69.906,130.786 73.984,130.786 TP6_PD.1@74.12,130.923 J17_PD.3@77.93,130.923
CS_HiSide_PE: J17_PE.3 TP6_PE.1 U5_PE.5 | length 14.6
  Top Layer w0.152: U5_PE.5@63.811,84.186 63.811,84.264 64.034,84.488 v7(65.682,84.488)
  Layer 5 w0.152: TP6_PE.1@73.916,84.774 TP6_PE.1@74.052,84.911
  Layer 6 w0.152: v7(65.682,84.488) 69.551,84.488 69.838,84.774 73.916,84.774 TP6_PE.1@74.052,84.911 J17_PE.3@77.862,84.911
CS_HiSide_PF: J17_PF.3 TP6_PF.1 U5_PF.5 | length 14.6
  Top Layer w0.152: U5_PF.5@63.797,38.262 63.797,38.34 64.021,38.564 v15(65.668,38.564)
  Layer 5 w0.152: TP6_PF.1@73.902,38.85 TP6_PF.1@74.038,38.986
  Layer 6 w0.152: v15(65.668,38.564) 69.538,38.564 69.824,38.85 73.902,38.85 TP6_PF.1@74.038,38.986 J17_PF.3@77.848,38.986
CS_InPhase_PA: J17_PA.1 TP12_PA.1 U7_PA.8 | length 42.3
  Top Layer w0.152: v5(113.034,135.045) U7_PA.8@113.034,136.35
  Layer 5 w0.152: TP12_PA.1@101.228,109.631 101.228,123.239 v5(113.034,135.045) v5@113.034,135.25
  Layer 6 w0.152: J17_PA.1@92.338,105.821 96.148,109.631 TP12_PA.1@101.228,109.631
CS_InPhase_PB: J17_PB.1 TP12_PB.1 U7_PB.8 | length 42.2
  Top Layer w0.152: v5(113.034,89.695) U7_PB.8@113.034,90.899
  Layer 6 w0.152: J17_PB.1@92.36,60.252 96.17,64.062 TP12_PB.1@101.25,64.062 101.25,77.911 v5(113.034,89.695)
CS_InPhase_PC: J17_PC.1 TP12_PC.1 U7_PC.8 | length 42.2
  Top Layer w0.152: v5(112.936,44.25) U7_PC.8@112.936,45.413
  Layer 5 w0.152: TP12_PC.1@101.13,18.576 101.13,21.214 111.614,31.697 111.614,42.928 v5(112.936,44.25)
  Layer 6 w0.152: J17_PC.1@92.24,14.766 96.05,18.576 TP12_PC.1@101.13,18.576
CS_InPhase_PD: J17_PD.1 TP12_PD.1 U7_PD.8 | length 44.4
  Top Layer w0.152: U7_PD.8@62.315,100.548 v5@62.315,101.712
  Layer 5 w0.152: v1(73.649,108.762) 73.649,121.454 74.12,121.925 TP12_PD.1@74.12,127.113
  Layer 6 w0.152: v5(62.315,101.713) 65.864,105.262 70.149,105.262 v1(73.649,108.762) ; TP12_PD.1@74.12,127.113 79.2,127.113 J17_PD.1@83.01,130.923
CS_InPhase_PE: J17_PE.1 TP12_PE.1 U7_PE.8 | length 44.5
  Top Layer w0.152: U7_PE.8@62.246,54.46 v5(62.246,55.607)
  Layer 5 w0.152: v1(73.581,62.75) 73.581,75.442 74.052,75.913 TP12_PE.1@74.052,81.101
  Layer 6 w0.152: v5(62.246,55.607) 65.889,59.25 70.081,59.25 v1(73.581,62.75) ; TP12_PE.1@74.052,81.101 79.132,81.101 J17_PE.1@82.942,84.911
CS_InPhase_PF: J17_PF.1 TP12_PF.1 U7_PF.8 | length 45.2
  Top Layer w0.152: v5(62.21,9.682) 62.221,9.672 62.221,8.547 U7_PF.8@62.232,8.536
  Layer 5 w0.152: v5(73.25,15.75) 73.25,15.818 73.5,16.068 73.5,18.561 73.25,18.811 73.25,19.293 73.5,19.543 73.5,34.081 74.038,34.62 TP12_PF.1@74.038,35.176
  Layer 6 w0.152: v5(62.21,9.682) 65.665,13.137 70.675,13.137 73.25,15.712 v5(73.25,15.75) ; TP12_PF.1@74.038,35.176 79.118,35.176 J17_PF.1@82.928,38.986
CS_PA: J17_PA.2 R7.1 | length 91.5
  Layer 5 w0.152: v1(148.043,87.869) 150.583,85.329 ; v1(150.583,59) 150.583,85.366
  Layer 6 w0.152: J17_PA.2@94.878,105.821 106.199,94.5 131.5,94.5 134,92 143.912,92 v1(148.043,87.869)
  Bottom Layer w0.152: R7.1@150.583,58.037 v1(150.583,59)
CS_PB: J17_PB.2 R10.1 | length 48.6
  Layer 6 w0.152: J17_PB.2@94.9,60.252 94.971,60.181 95.954,60.181 99.385,56.75 140.432,56.75 140.682,56.5 v1(140.75,56.5)
  Bottom Layer w0.152: v1(140.75,56.5) 141.836,56.5 R10.1@141.929,56.406
CS_PC: J17_PC.2 R11.1 | length 78.6
  Layer 5 w0.152: J17_PC.2@94.78,14.766 94.78,21.03 97.169,23.419 97.169,34.16 98.185,35.176 98.185,41.498 99.25,42.563 99.25,44.058 100.831,45.639 v1@100.831,45.851
  Layer 6 w0.152: v1(100.919,45.938) 107.678,45.938 108.116,45.5 117.355,45.5 118.298,44.557 129.039,44.557 130.42,45.938 142.151,45.938 v1(143.127,46.914)
  Bottom Layer w0.152: R11.1@142.157,47.495 142.157,47.47 142.556,47.071 142.846,47.071 143.003,46.914 v1(143.127,46.914)
CS_PD: J17_PD.2 R34.1 | length 74.3
  Top Layer w0.152: v1(82.287,59.25) 82.351,59.186 82.82,59.186 83.253,58.753 R34.1@83.253,58.036
  Layer 5 w0.152: J17_PD.2@80.47,130.923 80.47,98.625 81.655,97.441 81.655,82.594 81.855,82.393 81.855,59.681 v1(82.287,59.25)
CS_PE: J17_PE.2 R37.1 | length 27.4
  Layer 5 w0.152: J17_PE.2@80.402,84.911 81.25,84.062 v1(81.25,59.25)
  Bottom Layer w0.152: v1(81.25,59.25) 81.25,59.155 81.58,58.825 R37.1@81.58,58.036
CS_PF: J17_PF.2 R38.1 | length 9.1
  Layer 5 w0.152: v1(79.5,46.5) 79.5,39.874 J17_PF.2@80.388,38.986
  Bottom Layer w0.152: v1(79.5,46.5) R38.1@79.5,47.7
D1: C34.2 Q1_PA.1 Q1_PA.3 R104.1 | length 125.3
  Top Layer w0.152: v1(81.576,26.5) 81.664,26.587 81.664,26.932 82.482,27.75 R104.1@82.507,27.75 ; v5(122.373,117.26) 122.954,117.841 122.954,118.036 123.078,118.16 Q1_PA.3@123.228,118.16 123.329,118.16 123.453,118.283 Q1_PA.1@123.453,118.86
  Layer 5 w0.152: v1(81.576,26.5) 81.576,31.47 v1(83.794,33.687) ; v5(99.75,34.25) 101.75,36.25 101.75,41.989 101.739,42 101.739,43.739 108.25,50.25 108.25,63.25 110.5,65.5 v5(110.5,96.25) ; v5(116.5,96.75) 116.852,97.102 116.852,105.098 119.912,108.158 119.912,115.138 121.946,117.172 122.286,117.172 v5(122.373,117.26)
  Layer 6 w0.152: v1(83.794,33.687) 83.917,33.687 84.231,34 96.75,34 97,34.25 v5(99.75,34.25) ; v5(110.5,96.25) 111,96.75 v5(116.5,96.75)
  Bottom Layer w0.152: C34.2@81.375,25.25 81.576,25.451 v1(81.576,26.5)
D2: C32.2 Q1_PB.1 Q1_PB.3 R101.1 | length 75.9
  Top Layer w0.152: v1(85.296,26.75) 85.296,27.314 85.732,27.75 R101.1@85.757,27.75 ; v5(122.337,71.765) 122.425,71.853 122.584,71.853 123.246,72.516 Q1_PB.3@123.396,72.516 123.498,72.516 123.621,72.639 Q1_PB.1@123.621,73.216
  Layer 5 w0.152: v1(85.296,26.75) 85.296,28.796 86.25,29.75 v1(86.25,29.812) ; v1(103.5,30) 103.887,30.387 103.887,43.609 113.114,52.835 113.114,61.597 121.121,69.604 121.121,70.872 121.926,71.678 122.25,71.678 v5(122.337,71.765)
  Layer 6 w0.152: v1(86.25,29.812) 103.033,29.812 103.134,29.913 103.413,29.913 v1(103.5,30)
  Bottom Layer w0.152: v1(85.296,26.75) 85.308,26.737 85.308,26.217 86.275,25.25 C32.2@86.3,25.25
D3: C33.2 Q1_PC.1 Q1_PC.3 R103.1 | length 49.7
  Top Layer w0.152: R103.1@83.3,12.221 83.325,12.221 83.913,12.809 83.913,13.163 v1(84,13.25) ; v5(123.401,26.496) Q1_PC.3@123.401,27.222 123.502,27.222 123.626,27.346 Q1_PC.1@123.626,27.922
  Layer 6 w0.152: v1(84,13.25) 84.684,13.25 85.15,12.784 110.033,12.784 123.313,26.065 123.313,26.409 v5(123.401,26.496)
  Bottom Layer w0.152: C33.2@83.8,14.5 84,14.3 v1(84,13.25)
D4: C60.2 Q1_PD.1 Q1_PD.3 R108.1 | length 107
  Top Layer w0.152: Q1_PD.3@51.974,118.538 51.873,118.538 51.749,118.414 Q1_PD.1@51.749,117.838 51.798,117.789 51.798,117.524 52.282,117.039 v5(52.899,117.039) ; R108.1@77.612,27.75 77.612,26.986 v1(78.25,26.348)
  Layer 5 w0.152: v5(52.899,117.039) 52.938,117 53.25,117 59.898,110.352 59.898,101.352 75.25,86 75.5,85.75 75.5,80.491 75.131,80.121 75.131,57.363 75.419,57.075 75.419,36.831 78.25,34 v1(78.25,26.348)
  Bottom Layer w0.152: C60.2@78.205,25.25 78.25,25.295 v1(78.25,26.348)
D5: C58.2 Q1_PE.1 Q1_PE.3 R106.1 | length 67.4
  Top Layer w0.152: Q1_PE.3@51.905,72.942 51.804,72.942 51.68,72.818 Q1_PE.1@51.68,72.242 51.729,72.193 51.729,71.927 52.22,71.436 52.75,71.436 v5(52.754,71.432) ; R106.1@74.7,25.25 74.864,25.086 v1(74.864,24.25)
  Layer 5 w0.152: v5(52.754,71.432) 52.824,71.362 53.058,71.362 53.148,71.272 53.148,69.606 55.908,66.845 58.398,64.356 58.398,55.248 59.763,53.883 59.763,48.084 61.817,46.031 v5(61.817,32.75) ; v1(74.75,30.621) 74.807,30.564 74.807,24.307 v1(74.864,24.25)
  Layer 6 w0.152: v5(61.817,32.75) 61.817,32.695 62.75,31.762 62.75,31.75 68.312,31.75 69.062,31 74.5,31 74.5,30.995 74.75,30.745 v1(74.75,30.621)
  Bottom Layer w0.152: v1(74.864,24.25) 74.864,23.376 C58.2@74.95,23.29
D6: C45.2 Q1_PF.1 Q1_PF.3 R105.1 | length 34.1
  Top Layer w0.152: Q1_PF.3@51.892,26.648 51.79,26.648 51.667,26.524 Q1_PF.1@51.667,25.948 51.715,25.899 51.715,25.634 52.273,25.077 v5(52.865,25.077) ; R105.1@76.55,16.55 76.55,16.575 77.412,17.437 77.412,17.811 v5(77,18.223)
  Layer 6 w0.152: v5(52.865,25.077) 58.089,19.852 73.852,19.852 75.482,18.223 v5(77,18.223)
  Bottom Layer w0.152: v5(77,18.223) 77.026,18.223 77.587,17.663 77.587,17.488 78.5,16.575 C45.2@78.5,16.55
D-: C32.1 C33.1 C34.1 C45.1 C58.1 C59.1 C60.1 Q1_PA.2 Q1_PB.2 Q1_PC.2 Q1_PD.2 Q1_PE.2 Q1_PF.2 Q2.2 U8.4 U8.5 | length 498.8
  Top Layer w0.152: Q1_PF.2@52.117,25.948 52.148,25.917 52.846,25.917 v5(52.877,25.886) ; Q1_PE.2@52.13,72.242 v5(52.766,72.242) ; Q1_PD.2@52.199,117.838 52.212,117.852 52.886,117.852 v5(52.899,117.865) ; U8.4@82.598,14.873 82.598,14.055 v1@82.913,13.74 ; v1(83,13.5) 83.097,13.5 83.868,14.27 U8.5@83.868,14.873 ; v5(122.331,72.581) 122.842,73.092 123.123,73.092 123.171,73.141 Q1_PB.2@123.171,73.216 ; v5@122.461,118.333 122.764,118.636 122.854,118.636 123.003,118.785 Q1_PA.2@123.003,118.86 ; v5(122.513,26.504) 122.513,27.276 122.936,27.699 123.027,27.699 123.176,27.847 Q1_PC.2@123.176,27.922
  Layer 5 w0.152: v5(52.766,72.242) 53.5,71.508 53.5,69.752 58.276,64.975 58.75,64.502 58.75,55.394 60.148,53.996 60.148,48.2 60.549,47.799 60.549,47.797 62.169,46.177 62.169,33.219 62.398,32.991 62.398,32.219 61.94,31.762 v1(61.94,31.75) ; v5(52.899,117.865) 60.25,110.515 60.25,101.498 67.498,94.25 75.852,85.896 75.852,80.345 75.483,79.975 75.483,57.509 75.772,57.221 75.772,36.977 78.602,34.146 78.602,26.817 79.06,26.36 v1(79.06,26.348) 79.979,26.348 82.386,23.94 ; v1(75.388,30.123) 75.388,29.999 75.159,29.77 75.159,24.776 75.27,24.666 75.334,24.666 v1(75.75,24.25) 80.571,24.25 82.386,22.435 ; v1(83,13.5) 82.386,14.114 82.386,22.435 ; v1(84.558,26.348) 84.558,27.114 84.943,27.5 84.943,28.942 85.669,29.667 85.669,30.052 86.238,30.621 v1(86.25,30.621) ; v1(84.558,33.419) 84.434,33.419 84.121,33.106 83.711,33.106 81.929,31.324 81.929,26.969 82.386,26.512 v1(82.386,26.5) 82.386,23.94 ; v5(99.135,33.64) 99.135,34.457 99.509,34.831 99.833,34.831 101.386,36.385 101.386,43.894 101.551,44.058 101.56,44.058 107.898,50.396 107.898,63.396 110.148,65.646 110.148,95.602 109.598,96.152 v5(109.598,96.25) ; v1@102.879,30.48 v1(102.792,30.393) 102.916,30.393 103.193,30.67 103.5,30.67 103.5,43.72 112.761,52.981 112.761,61.743 120.768,69.75 120.768,71.018 v5(122.331,72.581) v5@122.373,72.623 ; v5(116,97.5) 116.121,97.5 116.5,97.879 116.5,105.244 119.56,108.304 119.56,115.284 v5(122.373,118.098) ; 82.386,22.435 82.386,23.94
  Layer 6 w0.152: v5(52.877,25.886) 53.5,25.263 53.5,24.94 58.212,20.228 75.364,20.228 76.54,19.052 77.421,19.052 79.723,16.75 v5(79.805,16.75) ; v1(61.94,31.75) 61.94,31.738 62.281,31.398 67.914,31.398 68.664,30.648 73.949,30.648 74.038,30.558 74.038,30.511 74.443,30.106 74.509,30.04 75.305,30.04 v1(75.388,30.123) ; v1(83,13.5) 83.025,13.5 83.39,13.864 84.568,13.864 85.296,13.137 109.887,13.137 122.513,25.763 v5(122.513,26.504) ; v1@84.75,33.648 v5(99.135,33.64) ; v1(86.25,30.621) 86.262,30.621 86.719,30.164 102.44,30.164 102.668,30.393 v1(102.792,30.393) ; v5(109.598,96.25) 110.45,97.102 115.535,97.102 115.933,97.5 v5(116,97.5)
  Bottom Layer w0.152: v1@75.837,23.977 76.525,23.29 C58.1@76.55,23.29 ; v1(79.06,26.348) 79.147,26.26 79.147,25.882 79.78,25.25 C60.1@79.805,25.25 ; v5(79.805,16.75) 79.742,16.687 79.742,16.217 78.5,14.975 C45.1@78.5,14.95 81.725,14.95 C33.1@82.175,14.5 ; v1(82.386,26.5) 82.386,25.839 82.551,25.674 82.551,25.649 82.95,25.25 C34.1@82.975,25.25 ; v1(83,13.5) 82.913,13.587 82.913,13.812 82.225,14.5 C33.1@82.2,14.5 C33.1@82.175,14.5 ; C34.1@83.275,25.25 C32.1@84.7,25.25 84.581,25.369 v1@84.581,26.078 ; Q2.2@86.975,3.6 86.926,3.649 86.926,3.951 86.877,4 86.877,6.06 86.549,6.388 82.451,10.486 82.451,11.588 81.7,12.339 C59.1@81.7,12.364 81.7,14.025 C33.1@82.175,14.5
DHL_PA: R84_PA.2 R86_PA.1 U6_PA.15 | length 15
  Top Layer w0.152: U6_PA.15@133.382,125.635 134.147,125.635 134.54,125.242 v1(134.552,125.242) ; R84_PA.2@133.537,136.43 133.936,136.031 134.293,136.031 R86_PA.1@135.57,134.754 ; R86_PA.1@135.6,135.031 135.625,135.006 135.625,134.788 135.868,134.788 136.157,134.499 136.157,134.256 v1(136.245,134.169)
  DC LINK Layer 2 w0.152: v1(134.552,125.242) 134.564,125.242 135.572,126.249 135.572,133.496 v1(136.245,134.169)
DHL_PB: R84_PB.2 R86_PB.1 U6_PB.15 | length 15
  Top Layer w0.152: U6_PB.15@133.404,80.066 134.169,80.066 134.562,79.673 v1(134.574,79.673) ; R84_PB.2@133.559,90.861 133.958,90.462 134.315,90.462 R86_PB.1@135.592,89.185 ; R86_PB.1@135.623,89.462 135.648,89.437 135.648,89.219 135.891,89.219 136.179,88.93 136.179,88.687 v1(136.267,88.6)
  DC LINK Layer 2 w0.152: v1(134.574,79.673) 134.586,79.673 135.594,80.68 135.594,87.927 v1(136.267,88.6)
DHL_PC: R84_PC.2 R86_PC.1 U6_PC.15 | length 15
  Top Layer w0.152: U6_PC.15@133.284,34.579 134.049,34.579 134.442,34.186 v1(134.454,34.186) ; R84_PC.2@133.439,45.374 133.838,44.975 134.195,44.975 R86_PC.1@135.472,43.698 ; R86_PC.1@135.502,43.975 135.527,43.95 135.527,43.732 135.77,43.732 136.059,43.443 136.059,43.2 v1(136.147,43.113)
  DC LINK Layer 2 w0.152: v1(134.454,34.186) 134.466,34.186 135.474,35.194 135.474,42.44 v1(136.147,43.113)
DHL_PD: R84_PD.2 R86_PD.1 U6_PD.15 | length 15
  Top Layer w0.152: v1(39.103,102.575) 39.191,102.488 39.191,102.245 39.48,101.956 39.723,101.956 39.723,101.738 R86_PD.1@39.748,101.713 ; R86_PD.1@39.778,101.99 41.055,100.713 41.412,100.713 R84_PD.2@41.811,100.314 ; v1(40.796,111.502) 40.808,111.502 41.201,111.109 U6_PD.15@41.966,111.109
  DC LINK Layer 2 w0.152: v1(39.103,102.575) 39.776,103.248 39.776,110.495 40.784,111.502 v1(40.796,111.502)
DHL_PE: R84_PE.2 R86_PE.1 U6_PE.15 | length 15
  Top Layer w0.152: v1(39.035,56.563) 39.122,56.476 39.122,56.233 39.411,55.944 39.654,55.944 39.654,55.726 R86_PE.1@39.679,55.701 ; R86_PE.1@39.71,55.978 40.987,54.701 41.344,54.701 R84_PE.2@41.743,54.302 ; v1(40.728,65.49) 40.74,65.49 41.133,65.097 U6_PE.15@41.898,65.097
  DC LINK Layer 2 w0.152: v1(39.035,56.563) 39.708,57.236 39.708,64.483 40.716,65.49 v1(40.728,65.49)
DHL_PF: R84_PF.2 R86_PF.1 U6_PF.15 | length 15
  Top Layer w0.152: v1(39.021,10.639) 39.109,10.552 39.109,10.309 39.397,10.02 39.64,10.02 39.64,9.802 R86_PF.1@39.665,9.777 ; R86_PF.1@39.696,10.054 40.973,8.777 41.33,8.777 R84_PF.2@41.729,8.378 ; v1(40.714,19.566) 40.726,19.566 41.119,19.173 U6_PF.15@41.884,19.173
  DC LINK Layer 2 w0.152: v1(39.021,10.639) 39.694,11.312 39.694,18.558 40.702,19.566 v1(40.714,19.566)
DLH_PA: R87_PA.2 R91_PA.1 U6_PA.16 | length 13.5
  Top Layer w0.152: U6_PA.16@133.382,126.036 133.397,126.051 v1(134.552,126.051) 134.51,126.093 133.423,126.093 U6_PA.16@133.382,126.135 ; R87_PA.2@133.549,134.734 133.574,134.734 134.244,134.064 134.465,134.064 v1(134.552,133.976) 134.639,133.889 134.772,133.889 135.57,133.091 R91_PA.1@135.595,133.091
  DC LINK Layer 2 w0.152: v1(134.552,126.051) 134.564,126.051 135.133,126.62 135.133,133.395 v1(134.552,133.976)
DLH_PB: R87_PB.2 R91_PB.1 U6_PB.16 | length 12.3
  Top Layer w0.152: U6_PB.16@133.404,80.566 133.446,80.524 134.533,80.524 v1(134.574,80.482) ; R87_PB.2@133.571,89.165 133.596,89.165 134.266,88.495 134.487,88.495 v1(134.574,88.407) 134.662,88.32 134.794,88.32 135.592,87.522 R91_PB.1@135.617,87.522
  DC LINK Layer 2 w0.152: v1(134.574,80.482) 134.586,80.482 135.155,81.051 135.155,87.826 v1(134.574,88.407)
DLH_PC: R87_PC.2 R91_PC.1 U6_PC.16 | length 13.5
  Top Layer w0.152: U6_PC.16@133.284,34.98 133.299,34.996 v1(134.454,34.996) 134.412,35.037 133.326,35.037 U6_PC.16@133.284,35.079 ; R87_PC.2@133.451,43.678 133.476,43.678 134.146,43.008 134.367,43.008 v1(134.454,42.921) 134.542,42.833 134.674,42.833 135.472,42.035 R91_PC.1@135.497,42.035
  DC LINK Layer 2 w0.152: v1(134.454,34.996) 134.466,34.996 135.035,35.565 135.035,42.34 v1(134.454,42.921)
DLH_PD: R87_PD.2 R91_PD.1 U6_PD.16 | length 13.5
  Top Layer w0.152: R91_PD.1@39.753,103.653 39.778,103.653 40.576,102.855 40.708,102.855 v1(40.796,102.767) 40.883,102.68 41.104,102.68 41.774,102.01 R87_PD.2@41.799,102.01 ; U6_PD.16@41.966,110.609 41.924,110.651 40.838,110.651 v1(40.796,110.693) 41.951,110.693 U6_PD.16@41.966,110.708
  DC LINK Layer 2 w0.152: v1(40.796,102.767) 40.215,103.348 40.215,110.124 40.784,110.693 v1(40.796,110.693)
DLH_PE: R87_PE.2 R91_PE.1 U6_PE.16 | length 13.5
  Top Layer w0.152: R91_PE.1@39.685,57.641 39.71,57.641 40.508,56.843 40.64,56.843 v1(40.728,56.756) 40.815,56.668 41.036,56.668 41.706,55.998 R87_PE.2@41.731,55.998 ; U6_PE.16@41.898,64.597 41.856,64.639 40.769,64.639 v1(40.728,64.681) 41.882,64.681 U6_PE.16@41.898,64.696
  DC LINK Layer 2 w0.152: v1(40.728,56.756) 40.147,57.337 40.147,64.112 40.716,64.681 v1(40.728,64.681)
DLH_PF: R87_PF.2 R91_PF.1 U6_PF.16 | length 13.5
  Top Layer w0.152: R91_PF.1@39.671,11.717 39.696,11.717 40.494,10.919 40.626,10.919 v1(40.714,10.831) 40.801,10.744 41.022,10.744 41.692,10.074 R87_PF.2@41.717,10.074 ; U6_PF.16@41.884,18.673 41.842,18.715 40.755,18.715 v1(40.714,18.756) 41.868,18.756 U6_PF.16@41.884,18.772
  DC LINK Layer 2 w0.152: v1(40.714,10.831) 40.133,11.412 40.133,18.187 40.702,18.756 v1(40.714,18.756)
EN3: R64.1 R66.2 TPS2.2 TPS2C.1 | length 6.5
  Top Layer w0.152: TPS2C.1@14.151,21.32 TPS2C.1@14.151,20.862 ; TPS2.2@14.217,19.14 14.151,19.206 TPS2C.1@14.151,20.862 ; R66.2@18.354,20.577 18.145,20.786 R64.1@16.429,20.786 14.227,20.786 TPS2C.1@14.151,20.862
EN5: R54.1 R58.2 TPS1.2 TPS1C.1 | length 6.1
  Top Layer w0.152: TPS1C.1@13.878,45.571 R54.1@15.985,45.571 R58.2@17.662,45.571
  Top Layer w0.254: TPS1C.1@13.793,46.243 13.83,46.206 13.83,44.036 TPS1.2@13.868,43.998
EN_HI_PA: C48_PA.1 R82_PA.1 U6_PA.18 | length 4.3
  Top Layer w0.152: U6_PA.18@133.382,127.135 133.413,127.166 134.035,127.166 134.879,128.01 134.879,128.067 135.484,128.067 R82_PA.1@135.557,128.14 ; R82_PA.1@135.548,128.156 R82_PA.1@135.573,128.156 R82_PA.1@135.557,128.14 ; C48_PA.1@135.557,126.528 R82_PA.1@135.557,128.14
EN_HI_PB: C48_PB.1 R82_PB.1 U6_PB.18 | length 4.3
  Top Layer w0.152: U6_PB.18@133.404,81.566 133.436,81.597 134.058,81.597 134.901,82.441 134.901,82.498 135.507,82.498 R82_PB.1@135.579,82.571 ; R82_PB.1@135.57,82.587 R82_PB.1@135.595,82.587 R82_PB.1@135.579,82.571 ; C48_PB.1@135.579,80.959 R82_PB.1@135.579,82.571
EN_HI_PC: C48_PC.1 R82_PC.1 U6_PC.18 | length 4.3
  Top Layer w0.152: U6_PC.18@133.284,36.079 133.315,36.11 133.938,36.11 134.781,36.954 134.781,37.012 135.387,37.012 R82_PC.1@135.459,37.084 ; R82_PC.1@135.45,37.1 R82_PC.1@135.475,37.1 R82_PC.1@135.459,37.084 ; C48_PC.1@135.459,35.472 R82_PC.1@135.459,37.084
EN_HI_PD: C48_PD.1 R82_PD.1 U6_PD.18 | length 4.3
  Top Layer w0.152: C48_PD.1@39.791,110.216 R82_PD.1@39.791,108.604 ; R82_PD.1@39.8,108.588 R82_PD.1@39.775,108.588 R82_PD.1@39.791,108.604 ; U6_PD.18@41.966,109.609 41.935,109.578 41.312,109.578 40.469,108.734 40.469,108.677 39.863,108.677 R82_PD.1@39.791,108.604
